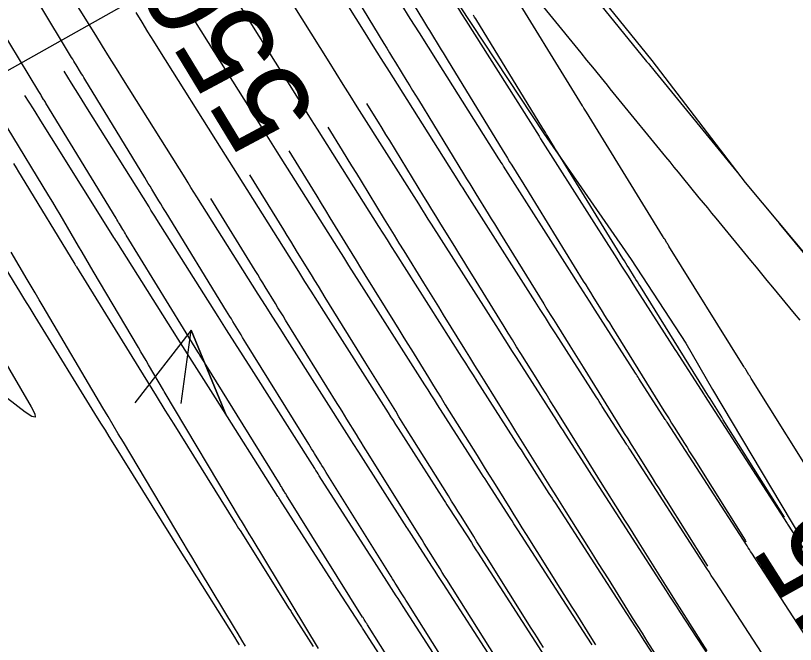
# Model space of a CAD drawing. Extents: x 954385 to 988206, y 1868364 to 1924553.
# Drawn here: x 957646.3 to 957697.2, y 1920153.2 to 1920194.2 of the extents above; entities that cross this region are included whole.
import ezdxf

# ---------------------------------------------------------------- set-up
doc = ezdxf.new("R2010")
doc.units = 0
for name, color, linetype in [('16', 7, 'Continuous'), ('24', 7, 'Continuous'), ('26', 7, 'Continuous'), ('5', 7, 'Continuous'), ('6', 7, 'Continuous'), ('7', 7, 'Continuous')]:
    doc.layers.add(name, color=color, linetype=linetype)

msp = doc.modelspace()

# ---------------------------------------------------------------- linework, layer by layer
at = {"layer": '16'}
for points in [[(957642.475, 1920245.119), (957647.904, 1920236.718), (957650.092, 1920233.249), (957653.344, 1920228.325), (957658.665, 1920219.852), (957664.238, 1920211.548), (957669.658, 1920203.141), (957675.294, 1920194.881), (957680.805, 1920186.536), (957686.502, 1920178.317), (957690.062, 1920172.865), (957691.817, 1920169.839), (957696.948, 1920161.236), (957702.103, 1920152.651)], [(957678.946, 1920149.871), (957674.227, 1920157.171), (957674.054, 1920157.439), (957673.881, 1920157.707), (957673.708, 1920157.975), (957673.536, 1920158.243), (957672.12, 1920160.445), (957672.056, 1920160.544), (957671.993, 1920160.643), (957671.929, 1920160.742), (957671.866, 1920160.841), (957668.719, 1920165.753), (957668.599, 1920165.94), (957668.48, 1920166.126), (957668.361, 1920166.313), (957668.242, 1920166.5), (957664.061, 1920173.068), (957663.585, 1920173.817), (957663.11, 1920174.566), (957662.635, 1920175.316), (957662.16, 1920176.066), (957658.154, 1920182.411), (957657.96, 1920182.718), (957657.767, 1920183.025), (957657.573, 1920183.333), (957657.38, 1920183.64), (957653.365, 1920190.048), (957652.909, 1920190.776), (957652.454, 1920191.505), (957652, 1920192.234), (957651.546, 1920192.963), (957647.583, 1920199.337)], [(957696.912, 1920149.765), (957692.03, 1920157.259), (957691.883, 1920157.485), (957691.736, 1920157.711), (957691.589, 1920157.937), (957691.443, 1920158.163), (957686.412, 1920165.946), (957686.359, 1920166.028), (957686.305, 1920166.111), (957686.252, 1920166.193), (957686.199, 1920166.276), (957684.617, 1920168.735), (957684.517, 1920168.891), (957684.417, 1920169.047), (957684.317, 1920169.203), (957684.217, 1920169.359), (957681.583, 1920173.471), (957681.244, 1920174.001), (957680.905, 1920174.531), (957680.567, 1920175.061), (957680.229, 1920175.591), (957675.817, 1920182.524), (957675.675, 1920182.747), (957675.533, 1920182.97), (957675.392, 1920183.193), (957675.251, 1920183.417), (957671.244, 1920189.761), (957670.718, 1920190.595), (957670.192, 1920191.43), (957669.667, 1920192.265), (957669.143, 1920193.1), (957665.131, 1920199.503)], [(957672.968, 1920198.29), (957674.612, 1920195.665), (957674.887, 1920195.228), (957675.161, 1920194.791), (957675.436, 1920194.354), (957675.712, 1920193.918), (957680.487, 1920186.357), (957680.511, 1920186.319), (957680.586, 1920186.201), (957685.024, 1920179.228), (957685.449, 1920178.56), (957685.875, 1920177.893), (957686.302, 1920177.225), (957686.729, 1920176.558), (957689.363, 1920172.446), (957689.399, 1920172.39), (957689.411, 1920172.371), (957691.265, 1920169.489), (957691.286, 1920169.456), (957696.692, 1920161.094), (957696.719, 1920161.052), (957701.051, 1920154.402)], [(957694.284, 1920148.303), (957689.685, 1920155.363), (957689.468, 1920155.697), (957689.251, 1920156.03), (957689.035, 1920156.364), (957688.819, 1920156.698), (957683.975, 1920164.191), (957683.898, 1920164.311), (957683.821, 1920164.43), (957683.744, 1920164.549), (957683.667, 1920164.669), (957682.221, 1920166.917), (957682.077, 1920167.142), (957681.932, 1920167.366), (957681.788, 1920167.591), (957681.645, 1920167.815), (957679.01, 1920171.928), (957678.715, 1920172.389), (957678.42, 1920172.85), (957678.126, 1920173.311), (957677.832, 1920173.773), (957673.466, 1920180.633), (957673.257, 1920180.961), (957673.049, 1920181.289), (957672.84, 1920181.618), (957672.633, 1920181.947), (957668.626, 1920188.291), (957668.166, 1920189.02), (957667.707, 1920189.749), (957667.248, 1920190.478), (957666.791, 1920191.208), (957662.778, 1920197.612)], [(957660.425, 1920195.721), (957664.438, 1920189.316), (957664.83, 1920188.692), (957665.222, 1920188.068), (957665.615, 1920187.444), (957666.008, 1920186.821), (957670.014, 1920180.477), (957670.289, 1920180.042), (957670.564, 1920179.609), (957670.839, 1920179.175), (957671.115, 1920178.741), (957675.434, 1920171.955), (957675.685, 1920171.562), (957675.935, 1920171.169), (957676.186, 1920170.776), (957676.437, 1920170.384), (957679.178, 1920166.106), (957679.312, 1920165.896), (957679.447, 1920165.685), (957679.583, 1920165.475), (957679.718, 1920165.265), (957681.134, 1920163.062), (957681.235, 1920162.906), (957681.336, 1920162.749), (957681.437, 1920162.593), (957681.538, 1920162.436), (957686.194, 1920155.233), (957686.48, 1920154.791), (957686.766, 1920154.35), (957687.053, 1920153.908), (957687.34, 1920153.467), (957691.656, 1920146.842)], [(957699.54, 1920151.226), (957694.374, 1920159.155), (957694.297, 1920159.274), (957694.221, 1920159.392), (957694.144, 1920159.51), (957694.067, 1920159.629), (957688.849, 1920167.701), (957688.82, 1920167.746), (957688.79, 1920167.792), (957688.761, 1920167.837), (957688.732, 1920167.882), (957687.014, 1920170.553), (957686.958, 1920170.641), (957686.902, 1920170.728), (957686.846, 1920170.815), (957686.79, 1920170.902), (957684.156, 1920175.015), (957683.773, 1920175.613), (957683.39, 1920176.212), (957683.008, 1920176.811), (957682.627, 1920177.41), (957678.168, 1920184.415), (957678.093, 1920184.533), (957678.018, 1920184.651), (957677.943, 1920184.769), (957677.869, 1920184.887), (957673.862, 1920191.231), (957673.269, 1920192.171), (957672.677, 1920193.111), (957672.086, 1920194.051), (957671.496, 1920194.992)], [(957654.162, 1920194.433), (957654.55, 1920193.809), (957654.939, 1920193.185), (957655.328, 1920192.562), (957655.718, 1920191.939), (957659.733, 1920185.532), (957659.992, 1920185.119), (957660.252, 1920184.706), (957660.512, 1920184.293), (957660.772, 1920183.881), (957664.778, 1920177.537), (957665.186, 1920176.892), (957665.594, 1920176.247), (957666.003, 1920175.603), (957666.413, 1920174.959), (957670.64, 1920168.318), (957670.802, 1920168.062), (957670.965, 1920167.807), (957671.128, 1920167.552), (957671.292, 1920167.297), (957674.303, 1920162.596), (957674.39, 1920162.46), (957674.478, 1920162.324), (957674.565, 1920162.188), (957674.652, 1920162.052), (957676.069, 1920159.849), (957676.217, 1920159.618), (957676.366, 1920159.388), (957676.515, 1920159.157), (957676.664, 1920158.926), (957681.289, 1920151.772)], [(957683.956, 1920153.171), (957683.631, 1920153.673), (957679.101, 1920160.681), (957678.976, 1920160.875), (957678.851, 1920161.068), (957678.726, 1920161.262), (957678.601, 1920161.456), (957677.185, 1920163.658), (957677.074, 1920163.831), (957676.963, 1920164.004), (957676.851, 1920164.178), (957676.74, 1920164.351), (957673.864, 1920168.841), (957673.657, 1920169.164), (957673.45, 1920169.488), (957673.244, 1920169.812), (957673.037, 1920170.136), (957668.764, 1920176.85), (957668.421, 1920177.389), (957668.079, 1920177.928), (957667.738, 1920178.467), (957667.396, 1920179.007), (957663.39, 1920185.351), (957663.063, 1920185.869), (957662.737, 1920186.387), (957662.411, 1920186.905), (957662.086, 1920187.424), (957658.072, 1920193.83), (957657.747, 1920194.348)], [(957676.603, 1920147.97), (957671.624, 1920155.673), (957671.51, 1920155.849), (957671.396, 1920156.026), (957671.282, 1920156.202), (957671.169, 1920156.379), (957669.587, 1920158.838), (957669.547, 1920158.9), (957669.508, 1920158.962), (957669.468, 1920159.024), (957669.428, 1920159.085), (957666.146, 1920164.21), (957666.07, 1920164.328), (957665.995, 1920164.445), (957665.92, 1920164.563), (957665.845, 1920164.681), (957661.71, 1920171.177), (957661.167, 1920172.031), (957660.625, 1920172.886), (957660.083, 1920173.741), (957659.542, 1920174.596), (957655.536, 1920180.941), (957655.408, 1920181.142), (957655.281, 1920181.344), (957655.155, 1920181.546), (957655.028, 1920181.748), (957651.012, 1920188.157), (957650.49, 1920188.99), (957649.97, 1920189.824), (957649.479, 1920190.611)], [(957674.261, 1920146.069), (957668.999, 1920154.208), (957668.955, 1920154.276), (957668.911, 1920154.345), (957668.867, 1920154.413), (957668.823, 1920154.482), (957667.054, 1920157.232), (957667.023, 1920157.281), (957666.991, 1920157.33), (957663.573, 1920162.666), (957663.542, 1920162.715), (957663.51, 1920162.764), (957663.479, 1920162.814), (957663.447, 1920162.863), (957659.359, 1920169.286), (957658.749, 1920170.245), (957658.14, 1920171.205), (957657.532, 1920172.165), (957656.924, 1920173.126), (957652.918, 1920179.471), (957652.857, 1920179.567), (957652.796, 1920179.663), (957652.736, 1920179.76), (957652.675, 1920179.856), (957648.659, 1920186.266), (957648.071, 1920187.204), (957647.485, 1920188.143), (957646.931, 1920189.032)], [(957660.944, 1920153.169), (957660.786, 1920153.42), (957660.628, 1920153.671), (957657.778, 1920158.203), (957657.627, 1920158.443), (957657.476, 1920158.683), (957657.326, 1920158.923), (957657.176, 1920159.164), (957652.693, 1920166.355), (957652.437, 1920166.765), (957652.182, 1920167.175), (957651.928, 1920167.586), (957651.674, 1920167.997), (957647.601, 1920174.599), (957647.264, 1920175.146), (957646.927, 1920175.693), (957646.591, 1920176.241), (957646.256, 1920176.789), (957642.304, 1920183.263), (957642.007, 1920183.75), (957641.711, 1920184.237), (957641.415, 1920184.725), (957641.119, 1920185.214), (957641.024, 1920185.371)], [(957646.178, 1920184.578), (957646.345, 1920184.308), (957646.512, 1920184.038), (957646.678, 1920183.767), (957650.186, 1920178.021), (957650.212, 1920177.977), (957650.239, 1920177.934), (957650.266, 1920177.89), (957650.293, 1920177.846), (957654.36, 1920171.255), (957654.928, 1920170.336), (957655.497, 1920169.417), (957656.067, 1920168.499), (957656.638, 1920167.582), (957660.609, 1920161.213), (957660.699, 1920161.069), (957660.79, 1920160.924), (957660.88, 1920160.78), (957660.97, 1920160.636), (957664.177, 1920155.537), (957664.217, 1920155.474), (957664.257, 1920155.41), (957664.297, 1920155.347), (957664.337, 1920155.283), (957665.737, 1920153.07)]]:
    msp.add_lwpolyline(points, dxfattribs=at)
at = {"layer": '24'}
msp.add_lwpolyline([(957645.505, 1920247.168), (957651.24, 1920238.975), (957657.104, 1920230.868), (957663.303, 1920222.989), (957669.266, 1920214.949), (957671.938, 1920211.601), (957675.531, 1920207.114), (957681.545, 1920199.11), (957687.849, 1920191.301), (957693.938, 1920183.347), (957700.39, 1920175.638), (957707.155, 1920168.141), (957713.84, 1920160.59), (957720.434, 1920152.977)], dxfattribs=at)
at = {"layer": '26'}
for points in [[(957607.131, 1920168.928), (957737.148, 1920242.007), (957734.089, 1920236.845), (957737.148, 1920242.007), (957731.149, 1920242.076)], [(957657.131, 1920168.928), (957657.771, 1920173.715), (957660.056, 1920168.167), (957657.771, 1920173.715), (957654.109, 1920168.962)]]:
    msp.add_lwpolyline(points, dxfattribs=at)
at = {"layer": '6'}
for points in [[(957681.864, 1920198.201), (957687.509, 1920191.25), (957687.556, 1920191.192), (957687.603, 1920191.135), (957687.65, 1920191.077), (957687.697, 1920191.02), (957687.979, 1920190.675), (957688.073, 1920190.56), (957693.431, 1920184.01)], [(957696.512, 1920161.502), (957692.519, 1920167.869), (957692.412, 1920168.041), (957692.304, 1920168.212), (957692.196, 1920168.384), (957692.088, 1920168.555), (957691.657, 1920169.241), (957691.549, 1920169.413), (957691.441, 1920169.584), (957691.334, 1920169.756), (957691.227, 1920169.928), (957687.102, 1920176.564), (957687.007, 1920176.716), (957686.913, 1920176.868), (957686.818, 1920177.02), (957686.723, 1920177.171), (957686.344, 1920177.778), (957686.25, 1920177.93), (957686.155, 1920178.082), (957686.061, 1920178.234), (957685.967, 1920178.386), (957681.713, 1920185.285), (957681.632, 1920185.417), (957681.551, 1920185.548), (957681.469, 1920185.68), (957681.388, 1920185.811), (957681.062, 1920186.337), (957680.981, 1920186.468), (957680.9, 1920186.6), (957680.819, 1920186.732), (957680.738, 1920186.863), (957676.353, 1920194.031), (957676.285, 1920194.142), (957676.217, 1920194.253)], [(957666.088, 1920152.935), (957661.759, 1920160.111), (957661.57, 1920160.424), (957661.256, 1920160.946), (957661.193, 1920161.05), (957661.13, 1920161.154), (957661.068, 1920161.259), (957661.005, 1920161.363), (957656.025, 1920169.709), (957655.998, 1920169.755), (957655.97, 1920169.802), (957654.998, 1920171.447), (957654.832, 1920171.729), (957654.665, 1920172.011), (957654.499, 1920172.292), (957654.332, 1920172.574), (957651.384, 1920177.566), (957651.144, 1920177.974), (957650.903, 1920178.383), (957650.664, 1920178.792), (957650.424, 1920179.201), (957649.468, 1920180.838), (957649.228, 1920181.247), (957648.986, 1920181.655), (957648.743, 1920182.061), (957648.497, 1920182.467), (957645.759, 1920186.957)], [(957664.164, 1920185.403), (957665.696, 1920182.909), (957665.982, 1920182.443), (957666.268, 1920181.977), (957666.553, 1920181.511), (957666.839, 1920181.045), (957667.98, 1920179.179), (957668.265, 1920178.713), (957668.552, 1920178.247), (957668.839, 1920177.782), (957669.126, 1920177.317), (957671.056, 1920174.203), (957671.332, 1920173.756), (957671.608, 1920173.31), (957671.884, 1920172.863), (957672.16, 1920172.416), (957673.262, 1920170.628), (957673.538, 1920170.182), (957673.815, 1920169.735), (957674.092, 1920169.289), (957674.37, 1920168.843), (957676.441, 1920165.525), (957676.708, 1920165.097), (957676.975, 1920164.669), (957677.242, 1920164.24), (957677.508, 1920163.812), (957678.574, 1920162.098), (957678.84, 1920161.67), (957679.108, 1920161.242), (957679.375, 1920160.814), (957679.644, 1920160.387), (957681.852, 1920156.878), (957682.11, 1920156.467), (957682.368, 1920156.057), (957682.626, 1920155.646), (957682.884, 1920155.235), (957683.915, 1920153.591), (957684.173, 1920153.18)], [(957696.171, 1920180.679), (957700.334, 1920175.626), (957700.361, 1920175.593), (957700.415, 1920175.529), (957706.66, 1920168.003), (957706.712, 1920167.94), (957706.765, 1920167.877), (957706.818, 1920167.814), (957706.87, 1920167.751), (957707.292, 1920167.247), (957713.061, 1920160.344), (957713.136, 1920160.254), (957713.211, 1920160.165), (957713.287, 1920160.075), (957713.362, 1920159.986), (957713.663, 1920159.628), (957713.814, 1920159.449), (957713.964, 1920159.27), (957719.523, 1920152.665)]]:
    msp.add_lwpolyline(points, dxfattribs=at)
at = {"layer": '7'}
for points in [[(957669.151, 1920200.144), (957672.948, 1920193.885), (957673.076, 1920193.676), (957673.203, 1920193.467), (957673.331, 1920193.258), (957673.459, 1920193.049), (957673.971, 1920192.215), (957674.099, 1920192.006), (957674.227, 1920191.798), (957674.355, 1920191.589), (957674.483, 1920191.38), (957678.149, 1920185.388), (957678.289, 1920185.158), (957678.43, 1920184.929), (957678.571, 1920184.701), (957678.713, 1920184.472), (957679.279, 1920183.558), (957679.421, 1920183.329), (957679.562, 1920183.101), (957679.703, 1920182.872), (957679.845, 1920182.643), (957683.38, 1920176.91), (957683.533, 1920176.661), (957683.687, 1920176.413), (957683.842, 1920176.164), (957683.996, 1920175.916), (957684.616, 1920174.924), (957684.77, 1920174.676), (957684.925, 1920174.428), (957685.08, 1920174.18), (957685.234, 1920173.931), (957688.641, 1920168.451), (957688.808, 1920168.183), (957688.975, 1920167.916), (957689.142, 1920167.649), (957689.31, 1920167.382), (957689.981, 1920166.315), (957690.149, 1920166.048), (957690.317, 1920165.781), (957690.484, 1920165.514), (957690.652, 1920165.247), (957693.935, 1920160.012), (957693.999, 1920159.91)], [(957667.279, 1920197.485), (957670.358, 1920192.41), (957670.545, 1920192.103), (957670.732, 1920191.796), (957670.92, 1920191.489), (957671.108, 1920191.182), (957671.861, 1920189.956), (957672.049, 1920189.649), (957672.237, 1920189.342), (957672.425, 1920189.036), (957672.613, 1920188.729), (957675.56, 1920183.912), (957675.76, 1920183.585), (957675.961, 1920183.259), (957676.162, 1920182.933), (957676.363, 1920182.607), (957677.17, 1920181.304), (957677.372, 1920180.979), (957677.574, 1920180.653), (957677.775, 1920180.327), (957677.976, 1920180.001), (957680.792, 1920175.434), (957681.006, 1920175.088), (957681.219, 1920174.743), (957681.434, 1920174.399), (957681.648, 1920174.054), (957682.508, 1920172.677), (957682.723, 1920172.333), (957682.937, 1920171.988), (957683.152, 1920171.644), (957683.366, 1920171.299), (957686.055, 1920166.974), (957686.282, 1920166.61), (957686.508, 1920166.248), (957686.735, 1920165.885), (957686.963, 1920165.523), (957687.874, 1920164.074), (957688.102, 1920163.712), (957688.33, 1920163.35), (957688.557, 1920162.988), (957688.784, 1920162.625), (957691.35, 1920158.533), (957691.486, 1920158.317)], [(957678.941, 1920197.059), (957683.208, 1920191.805), (957683.59, 1920191.335), (957683.972, 1920190.865), (957684.736, 1920189.924), (957684.927, 1920189.689), (957685.119, 1920189.454), (957685.31, 1920189.219), (957685.502, 1920188.984), (957688.743, 1920185.022), (957689.017, 1920184.688), (957689.29, 1920184.354), (957689.563, 1920184.02), (957689.836, 1920183.686), (957690.929, 1920182.349), (957691.203, 1920182.015), (957691.477, 1920181.682), (957691.751, 1920181.348), (957692.025, 1920181.015), (957694.3, 1920178.254), (957694.656, 1920177.822), (957695.013, 1920177.389), (957695.369, 1920176.957), (957695.725, 1920176.524), (957697.151, 1920174.794), (957697.508, 1920174.362)], [(957699.025, 1920163.094), (957694.387, 1920170.491), (957694.339, 1920170.567), (957694.291, 1920170.643), (957694.243, 1920170.72), (957694.195, 1920170.796), (957694.004, 1920171.1), (957693.956, 1920171.177), (957693.908, 1920171.253), (957693.86, 1920171.329), (957693.813, 1920171.406), (957688.969, 1920179.197), (957688.935, 1920179.252), (957688.9, 1920179.308), (957688.866, 1920179.363), (957688.831, 1920179.419), (957688.693, 1920179.64), (957688.658, 1920179.696), (957688.623, 1920179.751), (957688.589, 1920179.807), (957688.555, 1920179.863), (957683.581, 1920187.927), (957683.539, 1920187.996), (957683.497, 1920188.065), (957683.412, 1920188.202), (957683.39, 1920188.236), (957683.369, 1920188.27), (957683.348, 1920188.305), (957683.327, 1920188.339), (957678.223, 1920196.682)], [(957676.25, 1920149.013), (957671.88, 1920155.958), (957671.793, 1920156.096), (957671.706, 1920156.235), (957671.619, 1920156.375), (957671.532, 1920156.514), (957671.186, 1920157.071), (957671.099, 1920157.21), (957671.013, 1920157.349), (957670.926, 1920157.489), (957670.839, 1920157.628), (957666.602, 1920164.417), (957666.506, 1920164.571), (957666.409, 1920164.726), (957666.313, 1920164.881), (957666.218, 1920165.036), (957665.835, 1920165.657), (957665.739, 1920165.812), (957665.643, 1920165.967), (957665.547, 1920166.122), (957665.452, 1920166.277), (957661.354, 1920172.891), (957661.247, 1920173.063), (957661.141, 1920173.235), (957661.036, 1920173.407), (957660.93, 1920173.579), (957660.509, 1920174.268), (957660.404, 1920174.44), (957660.298, 1920174.612), (957660.193, 1920174.784), (957660.087, 1920174.956), (957656.138, 1920181.386), (957656.021, 1920181.576), (957655.905, 1920181.766), (957655.789, 1920181.957), (957655.673, 1920182.147), (957655.211, 1920182.909), (957655.095, 1920183.1), (957654.979, 1920183.29), (957654.863, 1920183.481), (957654.747, 1920183.671), (957650.842, 1920190.078), (957650.769, 1920190.197), (957650.697, 1920190.316), (957650.625, 1920190.435), (957650.553, 1920190.554), (957650.266, 1920191.031), (957650.194, 1920191.15), (957650.122, 1920191.27), (957650.05, 1920191.389), (957649.978, 1920191.508), (957647.84, 1920195.039)], [(957674.383, 1920146.391), (957669.293, 1920154.481), (957669.266, 1920154.524), (957669.239, 1920154.567), (957669.212, 1920154.609), (957669.185, 1920154.652), (957669.079, 1920154.824), (957669.052, 1920154.867), (957669.025, 1920154.91), (957668.999, 1920154.953), (957668.972, 1920154.995), (957664.013, 1920162.941), (957663.977, 1920162.999), (957663.941, 1920163.056), (957663.905, 1920163.114), (957663.869, 1920163.172), (957663.726, 1920163.404), (957663.691, 1920163.461), (957663.655, 1920163.519), (957663.619, 1920163.577), (957663.583, 1920163.635), (957658.763, 1920171.416), (957658.717, 1920171.49), (957658.671, 1920171.564), (957658.626, 1920171.638), (957658.58, 1920171.712), (957658.399, 1920172.009), (957658.354, 1920172.083), (957658.308, 1920172.157), (957658.263, 1920172.231), (957658.217, 1920172.305), (957653.546, 1920179.911), (957653.489, 1920180.003), (957653.433, 1920180.095), (957653.378, 1920180.186), (957653.322, 1920180.278), (957653.099, 1920180.645), (957653.043, 1920180.737), (957652.987, 1920180.829), (957652.932, 1920180.921), (957652.876, 1920181.012), (957648.3, 1920188.518), (957648.262, 1920188.58), (957648.224, 1920188.643), (957648.186, 1920188.706), (957648.148, 1920188.769), (957647.997, 1920189.02), (957647.959, 1920189.083), (957647.921, 1920189.146), (957647.883, 1920189.209), (957647.845, 1920189.272), (957645.315, 1920193.449)], [(957691.462, 1920152.791), (957691.162, 1920153.265), (957689.962, 1920155.158), (957689.662, 1920155.632), (957689.363, 1920156.106), (957689.064, 1920156.58), (957688.766, 1920157.055), (957686.917, 1920160.003), (957686.63, 1920160.461), (957686.342, 1920160.919), (957686.055, 1920161.376), (957685.767, 1920161.834), (957684.616, 1920163.663), (957684.328, 1920164.121), (957684.042, 1920164.579), (957683.755, 1920165.037), (957683.47, 1920165.496), (957681.499, 1920168.666), (957681.224, 1920169.107), (957680.95, 1920169.548), (957680.675, 1920169.989), (957680.4, 1920170.43), (957679.3, 1920172.192), (957679.026, 1920172.633), (957678.751, 1920173.074), (957678.478, 1920173.516), (957678.205, 1920173.958), (957676.108, 1920177.359), (957675.846, 1920177.782), (957675.585, 1920178.205), (957675.323, 1920178.628), (957675.062, 1920179.051), (957674.014, 1920180.742), (957673.752, 1920181.165), (957673.491, 1920181.588), (957673.231, 1920182.012), (957672.971, 1920182.436), (957670.743, 1920186.078), (957670.495, 1920186.483), (957670.247, 1920186.887), (957669.999, 1920187.292), (957669.751, 1920187.697), (957669.258, 1920188.5)], [(957666.711, 1920186.952), (957667.641, 1920185.437), (957667.949, 1920184.935), (957668.257, 1920184.432), (957668.565, 1920183.929), (957668.873, 1920183.426), (957670.382, 1920180.961), (957670.701, 1920180.439), (957671.022, 1920179.918), (957671.343, 1920179.397), (957671.664, 1920178.877), (957672.953, 1920176.798), (957673.275, 1920176.278), (957673.597, 1920175.757), (957673.918, 1920175.237), (957674.239, 1920174.716), (957675.618, 1920172.481), (957675.95, 1920171.943), (957676.283, 1920171.405), (957676.617, 1920170.867), (957676.952, 1920170.33), (957678.308, 1920168.157), (957678.635, 1920167.633), (957678.962, 1920167.108), (957679.289, 1920166.584), (957679.615, 1920166.059), (957680.921, 1920163.959), (957681.247, 1920163.435), (957681.575, 1920162.911), (957681.903, 1920162.387), (957682.232, 1920161.863), (957683.719, 1920159.5), (957684.037, 1920158.994), (957684.355, 1920158.488), (957684.673, 1920157.982), (957684.991, 1920157.475), (957686.261, 1920155.45), (957686.579, 1920154.944), (957686.897, 1920154.438), (957687.216, 1920153.933), (957687.536, 1920153.428), (957689.156, 1920150.873)], [(957680.777, 1920152.995), (957680.579, 1920153.31), (957680.381, 1920153.626), (957680.183, 1920153.941), (957679.985, 1920154.256), (957677.056, 1920158.91), (957676.848, 1920159.242), (957676.64, 1920159.573), (957676.433, 1920159.905), (957676.227, 1920160.237), (957675.401, 1920161.565), (957675.194, 1920161.897), (957674.988, 1920162.229), (957674.781, 1920162.561), (957674.574, 1920162.893), (957671.78, 1920167.368), (957671.563, 1920167.716), (957671.346, 1920168.065), (957671.13, 1920168.415), (957670.914, 1920168.764), (957670.052, 1920170.163), (957669.836, 1920170.513), (957669.62, 1920170.862), (957669.404, 1920171.212), (957669.188, 1920171.561), (957666.535, 1920175.842), (957666.308, 1920176.209), (957666.082, 1920176.577), (957665.856, 1920176.944), (957665.63, 1920177.312), (957664.729, 1920178.786), (957664.503, 1920179.154), (957664.278, 1920179.522), (957664.052, 1920179.89), (957663.826, 1920180.258), (957661.617, 1920183.855)], [(957678.118, 1920151.634), (957674.468, 1920157.434), (957674.321, 1920157.669), (957674.173, 1920157.904), (957674.026, 1920158.14), (957673.88, 1920158.375), (957673.293, 1920159.318), (957673.147, 1920159.554), (957673, 1920159.789), (957672.853, 1920160.025), (957672.706, 1920160.26), (957669.191, 1920165.892), (957669.034, 1920166.144), (957668.878, 1920166.396), (957668.722, 1920166.648), (957668.566, 1920166.9), (957667.943, 1920167.91), (957667.787, 1920168.162), (957667.632, 1920168.415), (957667.476, 1920168.667), (957667.32, 1920168.919), (957663.944, 1920174.367), (957663.778, 1920174.636), (957663.612, 1920174.906), (957663.446, 1920175.176), (957663.28, 1920175.446), (957662.619, 1920176.527), (957662.453, 1920176.797), (957662.288, 1920177.067), (957662.122, 1920177.337), (957661.957, 1920177.607), (957659.07, 1920182.307)], [(957661.324, 1920153.099), (957661.086, 1920153.493), (957660.848, 1920153.888), (957660.61, 1920154.282), (957658.386, 1920157.969), (957658.102, 1920158.441), (957657.818, 1920158.914), (957657.535, 1920159.387), (957657.252, 1920159.86), (957653.352, 1920166.396), (957653.018, 1920166.956), (957652.686, 1920167.515), (957652.354, 1920168.075), (957652.022, 1920168.635), (957648.11, 1920175.257), (957647.85, 1920175.699), (957647.59, 1920176.141), (957647.33, 1920176.583), (957647.071, 1920177.026), (957646.036, 1920178.798)], [(957645.216, 1920172.307), (957647.34, 1920168.711), (957647.578, 1920168.246), (957647.592, 1920168.033), (957647.382, 1920168.073), (957646.949, 1920168.364), (957644.142, 1920170.517)]]:
    msp.add_lwpolyline(points, dxfattribs=at)

# ---------------------------------------------------------------- texts
at = {"layer": '5'}
for s, rotation, p in [('550', 121.2914, (957666.171, 1920187.877)), ('545', 122.3572, (957706.501, 1920151.342))]:
    msp.add_text(s, height=6, rotation=rotation, dxfattribs=at).set_placement(p)

doc.saveas('drawing.dxf')
